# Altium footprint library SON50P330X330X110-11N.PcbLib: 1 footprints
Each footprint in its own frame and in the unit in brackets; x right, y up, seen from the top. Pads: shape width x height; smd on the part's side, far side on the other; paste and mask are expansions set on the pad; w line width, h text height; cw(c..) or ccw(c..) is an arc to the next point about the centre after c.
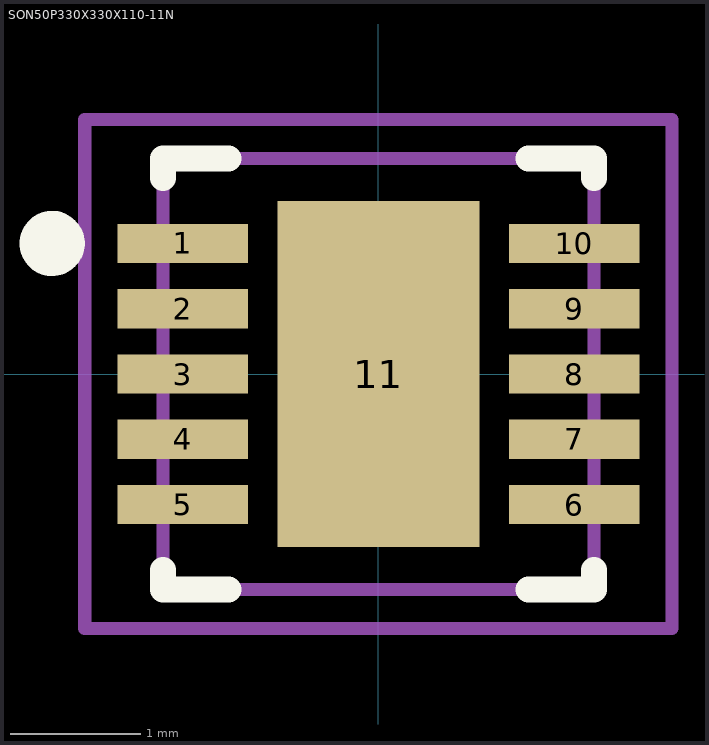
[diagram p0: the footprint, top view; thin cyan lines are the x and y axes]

## SON50P330X330X110-11N [mm] "SON,0.50mm pitch;10 pin,3.30mm W X 3.30mm L X 1.10mm H body (w/thermal tab)"
height 1.1
pads (11):
  rect 1x0.3 smd paste+0 mask+0: 1(-1.5,1) 2(-1.5,0.5) 3(-1.5,0) 4(-1.5,-0.5) 5(-1.5,-1) 6(1.5,-1) 7(1.5,-0.5) 8(1.5,0) 9(1.5,0.5) 10(1.5,1)
  rect 1.55x2.65 smd paste+0 mask+0: 11(0,0)
Top Overlay:
  circle w0.25: c-2.5,1 r0.125
  lines w0.2: -1.65,-1.5 -1.65,-1.65 -1.15,-1.65 ; -1.65,1.5 -1.65,1.65 -1.15,1.65 ; 1.15,-1.65 1.65,-1.65 1.65,-1.5 ; 1.15,1.65 1.65,1.65 1.65,1.5
Mechanical 3:
  text ".DESIGNATOR" at 0,0 h1.2
Mechanical 13:
  lines w0.1: -1.65,-1.65 -1.65,1.65 1.65,1.65 1.65,-1.65 -1.65,-1.65
Mechanical 15:
  lines w0.1: -0.5,0 0.5,0 ; 0,-0.5 0,0.5 ; -2.25,-1.95 2.25,-1.95 2.25,1.95 -2.25,1.95 -2.25,-1.95
3D body: height 1.06, standoff 0, extent -1.65,-1.65 1.65,1.65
